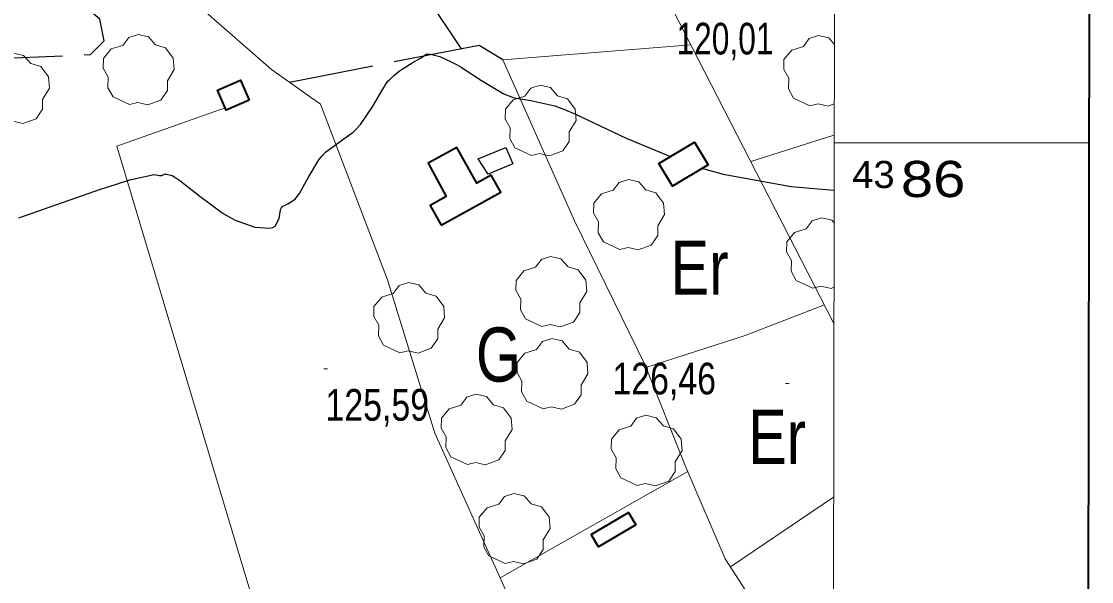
# Model space of a CAD drawing. Extents: x 487425 to 492029, y 4383576 to 4386788.
# Drawn here: x 491032.9 to 491328.9, y 4385878.7 to 4386033.6 of the extents above; entities that cross this region are included whole.
import ezdxf
from ezdxf.enums import TextEntityAlignment as Align

# ---------------------------------------------------------------- set-up
doc = ezdxf.new("R2010")
doc.units = 0
doc.header["$LTSCALE"] = 4
doc.linetypes.add('DOTTED', pattern=[1.5, 0.3, -1.2])
doc.linetypes.add('LONG_DASHED', pattern=[7.5, 6, -1.5])
for name, color, linetype, lineweight in [('1', 7, 'Continuous', 13), ('2', 7, 'DOTTED', 13), ('21', 7, 'Continuous', 25), ('25', 7, 'LONG_DASHED', 25), ('29', 7, 'Continuous', 13), ('47', 7, 'Continuous', 35), ('51', 7, 'Continuous', 13), ('7', 7, 'Continuous', 13), ('8', 7, 'Continuous', 25)]:
    doc.layers.add(name, color=color, linetype=linetype, lineweight=lineweight)
doc.layers.add('31', color=7, linetype='Continuous')

msp = doc.modelspace()

# ---------------------------------------------------------------- linework, layer by layer
at = {"layer": '1'}
msp.add_line((491257.67, 4386000), (491328.12, 4386000), dxfattribs=at)
at = {"layer": '1', "lineweight": 35}
msp.add_lwpolyline([(487611.46, 4386512.7), (491328.86, 4386507.3), (491325.3, 4384052.3), (487607.9, 4384057.7)], close=True, dxfattribs=at)
at = {"layer": '1'}
msp.add_lwpolyline([(487681.9, 4386441.2), (491258.2, 4386436), (491255.4, 4384123.8), (487678, 4384129)], close=True, dxfattribs=at)
at = {"layer": '21'}
msp.add_lwpolyline([(491159.24, 4385995.53), (491166.9, 4385998.74), (491168.84, 4385994.16), (491161.93, 4385991.33)], close=True, dxfattribs=at)
at = {"layer": '25'}
msp.add_line((491154.62, 4386026.01), (491109.5, 4386093.54), dxfattribs=at)
for points in [[(490912.89, 4386064.39), (490940.71, 4386056.93), (490963.85, 4386048.24), (490969.92, 4386045.74), (490987.51, 4386036.99), (490997.32, 4386031.94), (491011.55, 4386025.9), (491020.31, 4386023.02), (491051.96, 4386024.43), (491055.79, 4386028.16), (491054.61, 4386034.16), (491050.05, 4386037.93), (491043.84, 4386044.02), (491031.28, 4386053.88), (491027.25, 4386060.27), (491025.16, 4386065.07), (491041.97, 4386073.53)], [(491166.07, 4386022.96), (491159.49, 4386026.95), (491107.07, 4386016.72)]]:
    msp.add_lwpolyline(points, dxfattribs=at)
at = {"layer": '29'}
for p, q in [((491257.61, 4386027.38), (491257.71, 4386027.27)), ((491257.69, 4386010.77), (491257.59, 4386010.73)), ((491257.56, 4385977.94), (491257.65, 4385977.84)), ((491257.62, 4385960.07), (491257.54, 4385960.04))]:
    msp.add_line(p, q, dxfattribs=at)
for points in [[(491062.76, 4386010.55), (491058.22, 4386012.67), (491056.81, 4386015.21), (491056.91, 4386018.19), (491055.54, 4386020.6), (491055.58, 4386023.35), (491057.74, 4386025.95), (491060.93, 4386026.95), (491062.58, 4386029.14), (491065.15, 4386029.97), (491068.01, 4386029.32), (491069.96, 4386027.05), (491072.77, 4386026.23), (491074.9, 4386023.38), (491075.14, 4386020.25), (491073.26, 4386017.1), (491073.26, 4386014.42), (491071.44, 4386011.81), (491067.82, 4386010.47), (491065.05, 4386011.1)], [(491028.26, 4386005.4), (491023.72, 4386007.52), (491022.31, 4386010.06), (491022.41, 4386013.04), (491021.04, 4386015.45), (491021.08, 4386018.2), (491023.24, 4386020.8), (491026.43, 4386021.8), (491028.08, 4386023.99), (491030.65, 4386024.82), (491033.51, 4386024.17), (491035.46, 4386021.9), (491038.27, 4386021.08), (491040.4, 4386018.23), (491040.64, 4386015.1), (491038.76, 4386011.95), (491038.76, 4386009.27), (491036.94, 4386006.66), (491033.32, 4386005.32), (491030.55, 4386005.95)], [(491173.92, 4385996.5), (491169.38, 4385998.62), (491167.97, 4386001.16), (491168.07, 4386004.14), (491166.7, 4386006.55), (491166.74, 4386009.3), (491168.9, 4386011.9), (491172.09, 4386012.9), (491173.74, 4386015.09), (491176.31, 4386015.92), (491179.17, 4386015.27), (491181.12, 4386013), (491183.93, 4386012.18), (491186.06, 4386009.33), (491186.3, 4386006.2), (491184.42, 4386003.05), (491184.42, 4386000.37), (491182.6, 4385997.76), (491178.98, 4385996.42), (491176.21, 4385997.05)], [(491198.37, 4385970.48), (491193.83, 4385972.6), (491192.42, 4385975.14), (491192.52, 4385978.12), (491191.15, 4385980.53), (491191.19, 4385983.28), (491193.35, 4385985.88), (491196.54, 4385986.88), (491198.19, 4385989.07), (491200.76, 4385989.9), (491203.62, 4385989.25), (491205.57, 4385986.98), (491208.38, 4385986.16), (491210.51, 4385983.31), (491210.75, 4385980.18), (491208.87, 4385977.03), (491208.87, 4385974.35), (491207.05, 4385971.74), (491203.43, 4385970.4), (491200.66, 4385971.03)], [(491176.86, 4385949.17), (491172.32, 4385951.29), (491170.91, 4385953.83), (491171.01, 4385956.81), (491169.64, 4385959.22), (491169.68, 4385961.97), (491171.84, 4385964.57), (491175.03, 4385965.57), (491176.68, 4385967.76), (491179.25, 4385968.59), (491182.11, 4385967.94), (491184.06, 4385965.67), (491186.87, 4385964.85), (491189, 4385962), (491189.24, 4385958.87), (491187.36, 4385955.72), (491187.36, 4385953.04), (491185.54, 4385950.43), (491181.92, 4385949.09), (491179.15, 4385949.72)], [(491137.55, 4385941.93), (491133.01, 4385944.05), (491131.6, 4385946.59), (491131.7, 4385949.57), (491130.33, 4385951.98), (491130.37, 4385954.73), (491132.53, 4385957.33), (491135.72, 4385958.33), (491137.37, 4385960.52), (491139.94, 4385961.35), (491142.8, 4385960.7), (491144.75, 4385958.43), (491147.56, 4385957.61), (491149.69, 4385954.76), (491149.93, 4385951.63), (491148.05, 4385948.48), (491148.05, 4385945.8), (491146.23, 4385943.19), (491142.61, 4385941.85), (491139.84, 4385942.48)], [(491177.18, 4385926.45), (491172.64, 4385928.57), (491171.23, 4385931.11), (491171.33, 4385934.09), (491169.96, 4385936.5), (491170, 4385939.25), (491172.16, 4385941.85), (491175.35, 4385942.85), (491177, 4385945.04), (491179.57, 4385945.87), (491182.43, 4385945.22), (491184.38, 4385942.95), (491187.19, 4385942.13), (491189.32, 4385939.28), (491189.56, 4385936.15), (491187.68, 4385933), (491187.68, 4385930.32), (491185.86, 4385927.71), (491182.24, 4385926.37), (491179.47, 4385927)], [(491156.22, 4385911.06), (491151.68, 4385913.18), (491150.27, 4385915.72), (491150.37, 4385918.7), (491149, 4385921.11), (491149.04, 4385923.86), (491151.2, 4385926.46), (491154.39, 4385927.46), (491156.04, 4385929.65), (491158.61, 4385930.48), (491161.47, 4385929.83), (491163.42, 4385927.56), (491166.23, 4385926.74), (491168.36, 4385923.89), (491168.6, 4385920.76), (491166.72, 4385917.61), (491166.72, 4385914.93), (491164.9, 4385912.32), (491161.28, 4385910.98), (491158.51, 4385911.61)], [(491203.22, 4385905.23), (491198.68, 4385907.35), (491197.27, 4385909.89), (491197.37, 4385912.87), (491196, 4385915.28), (491196.04, 4385918.03), (491198.2, 4385920.63), (491201.39, 4385921.63), (491203.04, 4385923.82), (491205.61, 4385924.65), (491208.47, 4385924), (491210.42, 4385921.73), (491213.23, 4385920.91), (491215.36, 4385918.06), (491215.6, 4385914.93), (491213.72, 4385911.78), (491213.72, 4385909.1), (491211.9, 4385906.49), (491208.28, 4385905.15), (491205.51, 4385905.78)], [(491166.71, 4385883.66), (491162.17, 4385885.78), (491160.76, 4385888.32), (491160.86, 4385891.3), (491159.49, 4385893.71), (491159.53, 4385896.46), (491161.69, 4385899.06), (491164.88, 4385900.06), (491166.53, 4385902.25), (491169.1, 4385903.08), (491171.96, 4385902.43), (491173.91, 4385900.16), (491176.72, 4385899.34), (491178.85, 4385896.49), (491179.09, 4385893.36), (491177.21, 4385890.21), (491177.21, 4385887.53), (491175.39, 4385884.92), (491171.77, 4385883.58), (491169, 4385884.21)]]:
    msp.add_lwpolyline(points, close=True, dxfattribs=at)
for points in [[(491250.97, 4386010.23), (491246.43, 4386012.35), (491245.02, 4386014.89), (491245.12, 4386017.87), (491243.75, 4386020.28), (491243.79, 4386023.03), (491245.95, 4386025.63), (491249.14, 4386026.63), (491250.79, 4386028.82), (491253.36, 4386029.65), (491256.22, 4386029), (491257.61, 4386027.38)], [(491257.59, 4386010.73), (491256.03, 4386010.15), (491253.26, 4386010.78), (491250.97, 4386010.23)], [(491251.73, 4385959.84), (491247.19, 4385961.96), (491245.78, 4385964.5), (491245.88, 4385967.48), (491244.51, 4385969.89), (491244.55, 4385972.64), (491246.71, 4385975.24), (491249.9, 4385976.24), (491251.55, 4385978.43), (491254.12, 4385979.26), (491256.98, 4385978.61), (491257.56, 4385977.94)], [(491257.54, 4385960.04), (491256.79, 4385959.76), (491254.02, 4385960.39), (491251.73, 4385959.84)]]:
    msp.add_lwpolyline(points, dxfattribs=at)
at = {"layer": '47'}
for points in [[(491095.86, 4386011.77), (491089.5, 4386009.01), (491087.09, 4386014.57), (491093.45, 4386017.33)], [(491149, 4385977.26), (491165.44, 4385986.37), (491162.82, 4385991.08), (491158.81, 4385988.86), (491153.33, 4385998.74), (491145.34, 4385994.33), (491150.4, 4385985.14), (491145.94, 4385982.7)], [(491222.83, 4385993.94), (491212.94, 4385988), (491209.18, 4385994.27), (491219.07, 4386000.21)], [(491190.46, 4385891.74), (491200.79, 4385897.82), (491202.84, 4385894.33), (491192.51, 4385888.25)]]:
    msp.add_lwpolyline(points, close=True, dxfattribs=at)
at = {"layer": '51'}
for p, q in [((491257.58, 4386002.07), (491234.62, 4385994.83)), ((491257.67, 4386002.1), (491257.58, 4386002.07)), ((491257.52, 4385950.27), (491257.61, 4385950.09)), ((491165.28, 4385879.76), (491217.23, 4385909.09)), ((491228.99, 4385882.77), (491257.47, 4385902.06)), ((491257.47, 4385902.06), (491257.55, 4385902.12))]:
    msp.add_line(p, q, dxfattribs=at)
for points in [[(491130.69, 4386222.67), (491121.53, 4386217), (491213.05, 4386036.78), (491257.52, 4385950.27)], [(491072.35, 4386046.29), (491102.03, 4386020.3), (491108.39, 4386015.78), (491115.57, 4386010.65)], [(491257.39, 4385838.07), (491247.35, 4385854.32), (491227.56, 4385884.97), (491216.68, 4385910.34), (491205.28, 4385938.72), (491185.82, 4385978.44), (491166.07, 4386022.96), (491218.02, 4386027.12)], [(491115.57, 4386010.65), (491134.11, 4385962.08), (491147.27, 4385919.76), (491166.87, 4385876.21), (491205.94, 4385820.91), (491247.63, 4385764.41), (491203.82, 4385758.23)], [(491089.23, 4386009.66), (491059.3, 4385999.06), (491103.99, 4385849.87)], [(491205.62, 4385937.89), (491233.05, 4385946.74), (491255, 4385955.18)]]:
    msp.add_lwpolyline(points, dxfattribs=at)
at = {"layer": '7'}
for p, q in [((491116.5, 4385937.55), (491117.5, 4385937.55)), ((491244.21, 4385933.44), (491245.21, 4385933.44))]:
    msp.add_line(p, q, dxfattribs=at)
at = {"layer": '8'}
msp.add_line((491257.57, 4385986.88), (491257.66, 4385986.87), dxfattribs=at)
for points in [[(491032.21, 4385979.22), (491054.75, 4385987.14), (491059.2, 4385988.61), (491062.86, 4385989.75), (491069.59, 4385991.24), (491071.06, 4385990.92), (491071.41, 4385990.92), (491071.73, 4385990.96), (491072.67, 4385991.44), (491074.61, 4385990.93), (491075.56, 4385990.35), (491076.69, 4385989.57), (491082.27, 4385985.21), (491088.7, 4385980.49), (491090.38, 4385979.49), (491092, 4385978.64), (491097.45, 4385976.68), (491101.61, 4385976.4), (491102.4, 4385976.6), (491103.05, 4385976.92), (491104.13, 4385979.08), (491104.55, 4385981.5), (491104.79, 4385981.98), (491105.09, 4385982.38), (491106.58, 4385983.15), (491108.57, 4385984.43), (491109.17, 4385985.14), (491109.8, 4385986.02), (491112.25, 4385990.49), (491115.14, 4385995.33), (491116.04, 4385996.43), (491116.99, 4385997.43), (491120.76, 4386000.2), (491124.65, 4386002.97), (491125.67, 4386003.98), (491126.66, 4386005.09), (491130.02, 4386009.94), (491132.61, 4386014.4), (491133.12, 4386015.25), (491133.53, 4386015.94), (491134.24, 4386017.06), (491134.56, 4386017.32), (491134.72, 4386017.47), (491134.92, 4386017.65), (491135.9, 4386018.59), (491137.4, 4386019.83), (491137.92, 4386020.2), (491138.5, 4386020.59), (491140.97, 4386022.09), (491143.25, 4386023.43), (491143.71, 4386023.7), (491144.09, 4386023.94), (491144.83, 4386024.47), (491145.55, 4386024.54), (491145.92, 4386024.48), (491146.36, 4386024.4), (491148.57, 4386023.83), (491151.97, 4386022.34), (491153.18, 4386021.68), (491154.49, 4386020.9), (491160.17, 4386017.19), (491166.16, 4386013.65), (491167.67, 4386012.99), (491169.12, 4386012.47), (491173.81, 4386011.72), (491180.45, 4386010.21), (491183.12, 4386009.21), (491186.15, 4386007.96), (491200.11, 4386001.32), (491212.36, 4385996.18)], [(491221.15, 4385992.93), (491221.95, 4385992.68), (491226.95, 4385991.31), (491245.79, 4385987.91), (491257.57, 4385986.88)]]:
    msp.add_lwpolyline(points, dxfattribs=at)

# ---------------------------------------------------------------- texts
at = {"layer": '2'}
for s, height, width, p in [('43', 7.5, 1.05, (491262.66, 4385987.5)), ('86  ', 10, 1.2, (491276.11, 4385985))]:
    msp.add_text(s, height=height, dxfattribs=dict(at, width=width)).set_placement(p)
at = {"layer": '31', "width": 0.8}
for s, p in [('Er', (491220.41, 4385957.98)), ('G', (491164.83, 4385933.97)), ('Er', (491241.88, 4385911.23))]:
    msp.add_text(s, height=15, dxfattribs=at).set_placement(p, align=Align.CENTER)
at = {"layer": '7'}
for s, width, p in [('120,01', 0.75, (491214.05, 4386024.43)), ('126,46', 0.8, (491196.35, 4385930.44)), ('125,59', 0.8, (491117, 4385923.18))]:
    msp.add_text(s, height=8.75, dxfattribs=dict(at, width=width)).set_placement(p)

doc.saveas('drawing.dxf')
